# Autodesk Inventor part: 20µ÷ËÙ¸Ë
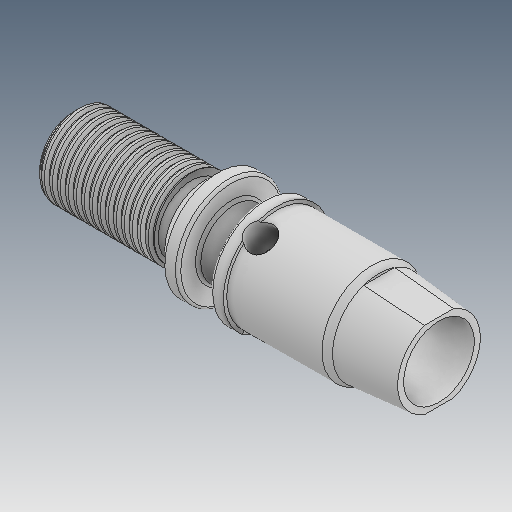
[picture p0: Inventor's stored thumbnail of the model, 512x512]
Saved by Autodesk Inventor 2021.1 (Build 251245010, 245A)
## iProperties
Created: 2019-04
Part Number: 20µ÷ËÙ¸Ë
Material: Ogólny
Document SubType Name: Modeling
Designer: user
Density: 1 g/cm^3
Appearance: Domyślna
Author: user
Revision Number: ÈÎºÎ
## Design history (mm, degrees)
feature "ÊäÈë1"
node "Bryła1"
